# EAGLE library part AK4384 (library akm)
Audio DAC 106dB, 192kHz, 24-Bit, 2ch, Delta Sigma DAC
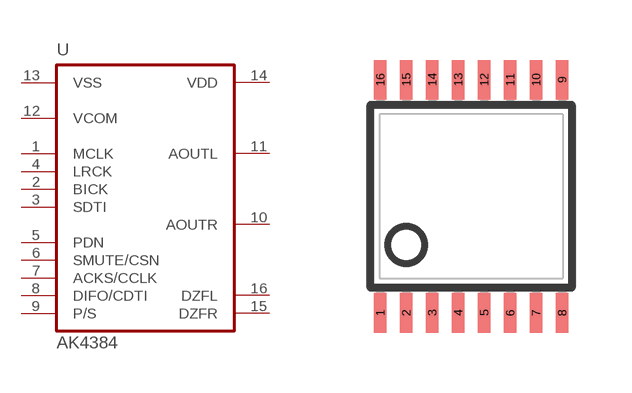
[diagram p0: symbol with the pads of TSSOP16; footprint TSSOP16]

Designator prefix U

## AK4384VT  [TSSOP16]
1  MCLK  in
2  BICK  in
3  SDTI  in
4  LRCK  in
5  PDN  in
6  SMUTE/CSN  in
7  ACKS/CCLK  in
8  DIFO/CDTI  in
9  P/S  in
10  AOUTR  pas
11  AOUTL  pas
12  VCOM  pas
13  VSS  pwr
14  VDD  pwr
15  DZFR  out
16  DZFL  out

## Footprint TSSOP16 (pad centres in mm)
TSSOP16
smd 0.305 x 0.991: 1 -2.275,-2.918; 2 -1.625,-2.918; 3 -0.975,-2.918; 4 -0.325,-2.918; 5 0.325,-2.918; 6 0.975,-2.918; 7 1.625,-2.918; 8 2.275,-2.918; 9 2.275,2.918; 10 1.625,2.918; 11 0.975,2.918; 12 0.325,2.918; 13 -0.325,2.918; 14 -0.975,2.918; 15 -1.625,2.918; 16 -2.275,2.918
